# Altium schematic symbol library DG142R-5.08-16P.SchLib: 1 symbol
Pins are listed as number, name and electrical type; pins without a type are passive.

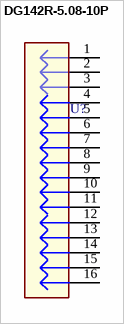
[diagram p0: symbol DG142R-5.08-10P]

## DG142R-5.08-10P
designator U?  (value not drawn)
DG129-5.0-03P-14-00AH
footprint DG142R-5.08-16P
pins: 1, 2, 3, 4, 5, 6, 7, 8, 9, 10, 11, 12, 13, 14, 15, 16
